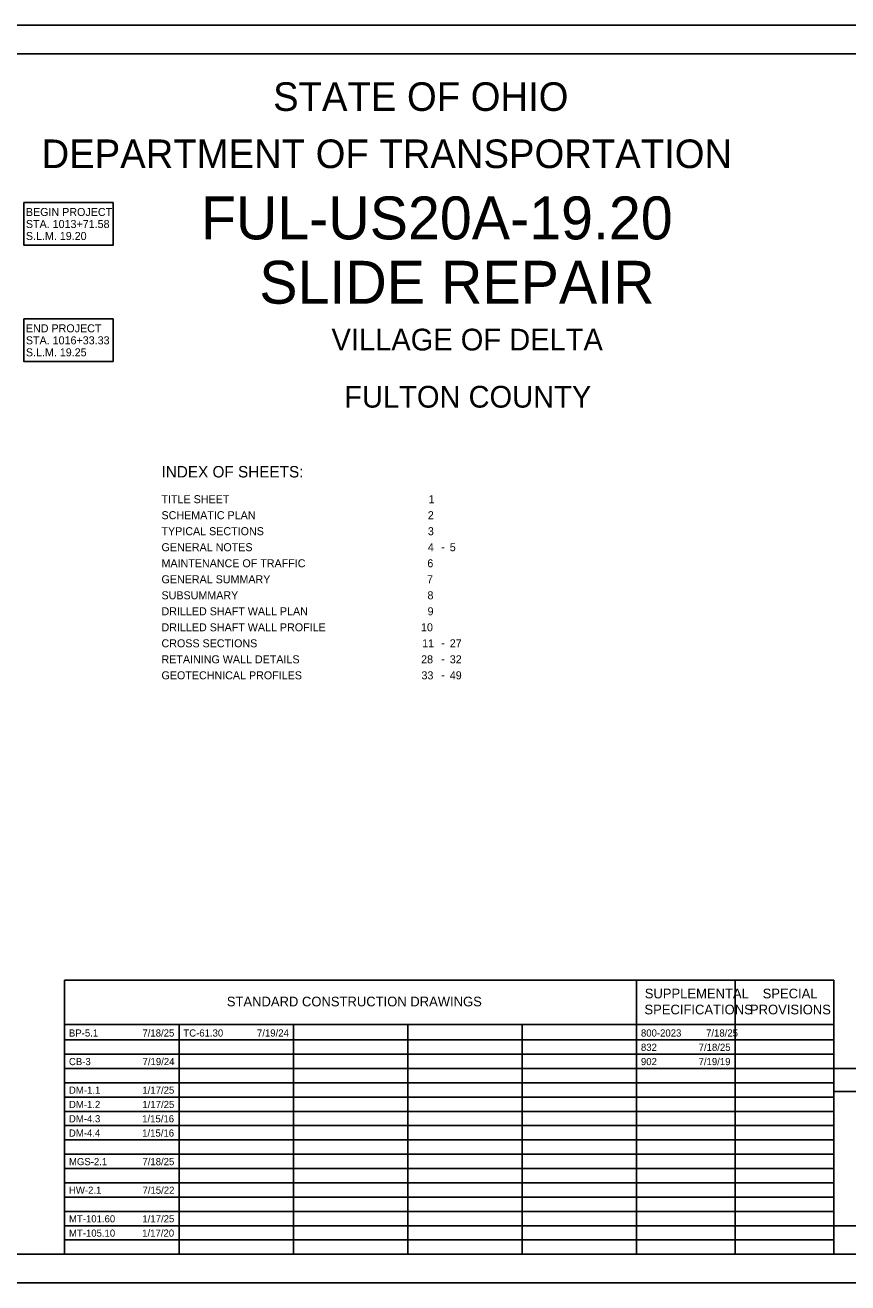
# Model space of a CAD drawing. Extents: x 0 to 42, y 0 to 22.
# Drawn here: x 9.46 to 23.84, y 0 to 22 of the extents above; entities that cross this region are included whole.
import ezdxf

# ---------------------------------------------------------------- set-up
doc = ezdxf.new("R2010")
doc.units = 0
for name, color, linetype in [('SH_Border', 7, 'Continuous'), ('SH_Cut_Line', 7, 'Continuous'), ('SH_Data', 7, 'Continuous'), ('SH_Text', 7, 'Continuous')]:
    doc.layers.add(name, color=color, linetype=linetype)

msp = doc.modelspace()

# ---------------------------------------------------------------- linework, layer by layer
at = {"layer": 'SH_Border'}
msp.add_lwpolyline([(1.5, 21.5), (33.5, 21.5), (33.5, 0.5), (1.5, 0.5)], close=True, dxfattribs=at)
at = {"layer": 'SH_Cut_Line'}
msp.add_lwpolyline([(0, 0), (34, 0), (34, 22), (0, 22)], close=True, dxfattribs=at)
at = {"layer": 'SH_Data'}
for p, q in [((10.15, 5.292), (23.6, 5.292)), ((10.15, 0.5), (10.15, 5.292)), ((20.15, 0.5), (20.15, 5.292)), ((21.875, 0.5), (21.875, 5.292)), ((23.6, 0.5), (23.6, 5.292)), ((10.15, 4.521), (23.6, 4.521)), ((12.15, 0.5), (12.15, 4.521)), ((14.15, 0.5), (14.15, 4.521)), ((16.15, 0.5), (16.15, 4.521)), ((18.15, 0.5), (18.15, 4.521)), ((10.15, 4.25), (23.6, 4.25)), ((10.15, 4), (23.6, 4)), ((10.15, 3.75), (23.6, 3.75)), ((23.6, 0.5), (23.6, 3.75)), ((23.6, 3.75), (26.4, 3.75)), ((10.15, 3.5), (23.6, 3.5)), ((23.6, 3.35), (26.4, 3.35)), ((10.15, 3.25), (23.6, 3.25)), ((10.15, 3), (23.6, 3)), ((10.15, 2.75), (23.6, 2.75)), ((10.15, 2.5), (23.6, 2.5)), ((10.15, 2.25), (23.6, 2.25)), ((10.15, 2), (23.6, 2)), ((10.15, 1.75), (23.6, 1.75)), ((10.15, 1.5), (23.6, 1.5)), ((10.15, 1.25), (23.6, 1.25)), ((10.15, 1), (23.6, 1)), ((10.15, 0.75), (23.6, 0.75)), ((23.6, 0.5), (26.4, 0.5))]:
    msp.add_line(p, q, dxfattribs=at)
msp.add_lwpolyline([(23.6, 0.5), (23.6, 1), (26.4, 1), (26.4, 0.5)], close=True, dxfattribs=at)
at = {"layer": 'SH_Text'}
for points in [[(9.439, 18.895), (10.998, 18.895), (10.998, 18.149), (9.439, 18.149)], [(9.439, 16.86), (10.998, 16.86), (10.998, 16.114), (9.439, 16.114)]]:
    msp.add_lwpolyline(points, close=True, dxfattribs=at)

# ---------------------------------------------------------------- texts
for s, height, p in [('STATE OF OHIO', 0.5, (13.795, 20.5)), ('DEPARTMENT OF TRANSPORTATION', 0.5, (9.747, 19.5)), ('FUL-US20A-19.20', 0.75, (12.531, 18.253)), ('BEGIN PROJECT', 0.14, (9.473, 18.662)), ('STA. 1013+71.58', 0.14, (9.473, 18.452)), ('S.L.M. 19.20', 0.14, (9.473, 18.242)), ('SLIDE REPAIR', 0.75, (13.553, 17.128)), ('END PROJECT', 0.14, (9.473, 16.627)), ('STA. 1016+33.33', 0.14, (9.473, 16.417)), ('  VILLAGE OF DELTA  ', 0.38, (14.534, 16.31)), ('S.L.M. 19.25', 0.14, (9.473, 16.207)), ('    FULTON COUNTY   ', 0.38, (14.474, 15.31)), ('INDEX OF SHEETS:', 0.2, (11.844, 14.088)), ('TITLE SHEET', 0.14, (11.844, 13.638)), ('1', 0.14, (16.513, 13.638)), ('SCHEMATIC PLAN', 0.14, (11.844, 13.358)), ('2', 0.14, (16.5, 13.358)), ('TYPICAL SECTIONS', 0.14, (11.844, 13.078)), ('3', 0.14, (16.501, 13.078)), ('GENERAL NOTES', 0.14, (11.844, 12.798)), ('4', 0.14, (16.501, 12.798)), ('-', 0.14, (16.736, 12.802)), ('5', 0.14, (16.884, 12.798)), ('MAINTENANCE OF TRAFFIC', 0.14, (11.844, 12.517)), ('6', 0.14, (16.492, 12.517)), ('GENERAL SUMMARY', 0.14, (11.844, 12.237)), ('7', 0.14, (16.486, 12.237)), ('SUBSUMMARY', 0.14, (11.844, 11.957)), ('8', 0.14, (16.494, 11.957)), ('DRILLED SHAFT WALL PLAN', 0.14, (11.844, 11.677)), ('9', 0.14, (16.496, 11.677)), ('DRILLED SHAFT WALL PROFILE', 0.14, (11.844, 11.397)), ('10', 0.14, (16.381, 11.397)), ('CROSS SECTIONS', 0.14, (11.844, 11.117)), ('11', 0.14, (16.401, 11.117)), ('27', 0.14, (16.884, 11.117)), ('-', 0.14, (16.736, 11.122)), ('RETAINING WALL DETAILS', 0.14, (11.844, 10.837)), ('28', 0.14, (16.383, 10.837)), ('-', 0.14, (16.736, 10.842)), ('32', 0.14, (16.884, 10.837)), ('GEOTECHNICAL PROFILES', 0.14, (11.844, 10.557)), ('33', 0.14, (16.389, 10.557)), ('-', 0.14, (16.736, 10.562)), ('49', 0.14, (16.884, 10.557)), ('SUPPLEMENTAL', 0.17, (20.293, 4.976)), ('SPECIAL', 0.17, (22.354, 4.976)), ('STANDARD CONSTRUCTION DRAWINGS', 0.17, (12.986, 4.836)), ('SPECIFICATIONS', 0.17, (20.287, 4.696)), ('PROVISIONS', 0.17, (22.132, 4.696)), ('BP-5.1', 0.125, (10.226, 4.308)), ('7/18/25', 0.125, (11.51, 4.308)), ('TC-61.30', 0.125, (12.226, 4.308)), ('7/19/24', 0.125, (13.513, 4.308)), ('800-2023', 0.125, (20.226, 4.308)), ('7/18/25', 0.125, (21.365, 4.308)), ('832', 0.125, (20.226, 4.058)), ('7/18/25', 0.125, (21.235, 4.058)), ('CB-3', 0.125, (10.226, 3.808)), ('7/19/24', 0.125, (11.513, 3.808)), ('902', 0.125, (20.226, 3.808)), ('7/19/19', 0.125, (21.234, 3.808)), ('DM-1.1', 0.125, (10.226, 3.308)), ('1/17/25', 0.125, (11.51, 3.308)), ('DM-1.2', 0.125, (10.226, 3.058)), ('1/17/25', 0.125, (11.51, 3.058)), ('DM-4.3', 0.125, (10.226, 2.808)), ('1/15/16', 0.125, (11.506, 2.808)), ('DM-4.4', 0.125, (10.226, 2.558)), ('1/15/16', 0.125, (11.506, 2.558)), ('MGS-2.1', 0.125, (10.226, 2.058)), ('7/18/25', 0.125, (11.51, 2.058)), ('HW-2.1', 0.125, (10.226, 1.558)), ('7/15/22', 0.125, (11.512, 1.558)), ('MT-101.60', 0.125, (10.226, 1.058)), ('1/17/25', 0.125, (11.51, 1.058)), ('MT-105.10', 0.125, (10.226, 0.808)), ('1/17/20', 0.125, (11.507, 0.808))]:
    msp.add_text(s, height=height, dxfattribs=at).set_placement(p)

doc.saveas('drawing.dxf')
